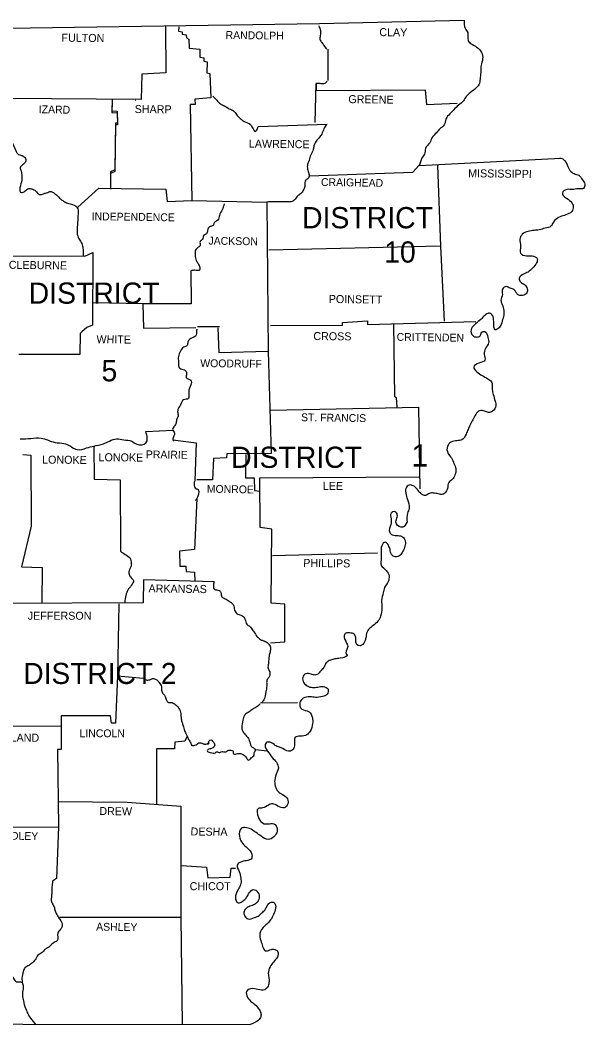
# Model space of a CAD drawing. Extents: x -33639 to 34530, y -17264 to 5867.
# Drawn here: x -15961 to -14292, y 2895 to 5867 of the extents above; entities that cross this region are included whole.
import ezdxf

# ---------------------------------------------------------------- set-up
doc = ezdxf.new("R2010")
doc.units = 0
for name, color, linetype in [('1', 7, 'Continuous'), ('2', 7, 'Continuous'), ('3', 7, 'Continuous')]:
    doc.layers.add(name, color=color, linetype=linetype)

msp = doc.modelspace()

# ---------------------------------------------------------------- linework, layer by layer
at = {"layer": '1'}
for p, q in [((-14780.6, 5436.9), (-14774, 5457.3)), ((-14779, 5443.5), (-14772.4, 5459.5)), ((-15436.7, 4960.3), (-15371.2, 4960.3)), ((-15250.6, 3847.5), (-15140.6, 3849.1))]:
    msp.add_line(p, q, dxfattribs=at)
for points in [[(-17667.8, 5841.4), (-16777.9, 5840.9), (-15996.9, 5842.5), (-15075.6, 5856.8), (-14648.6, 5866.7)], [(-15530.8, 5847.5), (-15529.7, 5711), (-15601.2, 5707.1), (-15603.4, 5632.3), (-16001.3, 5634.5)], [(-15491.2, 5846.9), (-15492.8, 5833.7), (-15481.8, 5832.1), (-15482.3, 5825.5), (-15469.7, 5822.7), (-15468.6, 5813.9), (-15462.5, 5810.1), (-15460.9, 5783.6), (-15429.5, 5780.3), (-15429.5, 5756.7), (-15418, 5755), (-15418, 5745.7), (-15408, 5742.9), (-15408.6, 5711), (-15399.8, 5709.3), (-15397.6, 5637.2), (-15444.4, 5632.8), (-15443.8, 5617.4), (-15458.1, 5616.9), (-15453.2, 5332.9), (-15231.4, 5327.9), (-15227.5, 4886.6), (-15372.3, 4882.7), (-15375, 4957)], [(-15051.4, 5780.9), (-15051.4, 5687.9)], [(-15088.8, 5564.1), (-15086.1, 5679.1), (-15086.1, 5658.7), (-14764.1, 5660.4), (-14759.7, 5617.4), (-14668.9, 5620.7)], [(-15688.2, 5630.6), (-15689.3, 5598.7), (-15673.9, 5597.6), (-15673.3, 5562.4), (-15678.8, 5562.4), (-15681, 5423.7), (-15693.7, 5418.2), (-15693.7, 5372)], [(-15688.2, 5625.7), (-15689.3, 5593.8), (-15673.9, 5592.7), (-15673.3, 5557.4), (-15678.8, 5557.4), (-15681, 5418.8), (-15693.7, 5413.3), (-15693.7, 5367)], [(-15619.4, 5629.5), (-15618.8, 5630.1)], [(-15257.3, 5551.9), (-15053.1, 5559.1)], [(-14780.6, 5436.9), (-14362.9, 5458.4)], [(-15105.4, 5406.7), (-14799.9, 5416.6), (-14781.7, 5437.5)], [(-14727.8, 5436.4), (-14718.5, 5198.1), (-14707.4, 4976.3)], [(-15790.5, 5313.1), (-15727.8, 5369.8), (-15529.7, 5367), (-15525.8, 5330.2), (-15453.7, 5332.9)], [(-15159.3, 5329.1), (-15226.4, 5329.1), (-15231.4, 5327.9)], [(-16052.5, 5170), (-15769.6, 5168.3), (-15745.4, 5179.9), (-15747.1, 4964.7), (-15763.6, 4957.6), (-15778.4, 4944.9), (-15783.4, 4940), (-15783.9, 4878.3), (-15963.9, 4878.3)], [(-14718.5, 5198.1), (-15225.3, 5186.5)], [(-15455.9, 5124.9), (-15454.8, 5028), (-15597.9, 5027.5), (-15744.9, 5030.2)], [(-15597.9, 5027.5), (-15595.7, 4955.4), (-15441.1, 4958.1)], [(-15220.9, 4963.6), (-15008.5, 4964.7), (-15007.9, 4972.4), (-14934.2, 4977.9), (-14934.2, 4966.4), (-14613.9, 4975.2)], [(-14857.1, 4966.4), (-14854.4, 4754.5), (-14849.4, 4751.2), (-14847.8, 4722.6)], [(-15436.7, 4951), (-15439.4, 4950.4)], [(-15227.5, 4886.6), (-15219.3, 4585), (-15350.3, 4584.4), (-15350.8, 4572.3), (-15388.8, 4570.1), (-15392.1, 4507.4), (-15438.3, 4507.4)], [(-15220.9, 4713.2), (-14783.9, 4722)], [(-14783.9, 4722), (-14779.5, 4481)], [(-15589.1, 4650.5), (-15508.8, 4654.3)], [(-15509.3, 4625.7), (-15440.5, 4616.9), (-15444.4, 4504.6)], [(-15952.9, 4581.7), (-15928.7, 4580), (-15928.1, 4369.8), (-15956.8, 4250.4), (-15895.7, 4247.6), (-15896.2, 4142.4)], [(-15743.2, 4605.5), (-15742.1, 4509), (-15664.5, 4507.4), (-15664, 4296)], [(-15294.1, 4581.7), (-15294.7, 4513.4), (-15269.4, 4513.4), (-15268.3, 4475.5), (-15252.3, 4473.8)], [(-15220.9, 4025.3), (-15178, 4028), (-15178.6, 4139.7), (-15218.7, 4142.5), (-15216.5, 4361), (-15251.2, 4365.9), (-15252.3, 4512.9), (-14782.8, 4516.2)], [(-15438.3, 4451.8), (-15444.9, 4301), (-15490.1, 4296), (-15489, 4251.5), (-15470.8, 4252), (-15470.2, 4236.6), (-15445.5, 4233.8), (-15444.7, 4207.3)], [(-15215.4, 4283.4), (-14905, 4291.1)], [(-15387.7, 4205.8), (-15595.7, 4211.3), (-15596.8, 4143.6), (-16017.8, 4141.9)], [(-15668.9, 4140.3), (-15673.3, 3927.3), (-15596.8, 3921.2)], [(-15673.3, 3927.3), (-15678.3, 3787.5), (-15690.9, 3787.5), (-15693.1, 3809), (-15839.5, 3809), (-15839.5, 3778.2)], [(-16035.5, 3779.8), (-15840.6, 3778.7)], [(-15839.5, 3778.7), (-15839, 3709.9), (-15850.5, 3709.4), (-15847.2, 3481)], [(-15467.5, 3749.5), (-15474.1, 3734.7), (-15503.3, 3731.9), (-15504.9, 3712.1), (-15557.2, 3712.1), (-15557.7, 3547.6)], [(-15405.8, 3725.3), (-15404.2, 3727), (-15402.5, 3728.6), (-15402.5, 3728.6)], [(-15848.9, 3555.8), (-15644.7, 3554.2), (-15486.2, 3542.1)], [(-15486.2, 3542.1), (-15486.2, 3212.9), (-15481.8, 2896.5)], [(-16096, 3480.4), (-15847.2, 3481)], [(-15847.2, 3481), (-15852.7, 3328), (-15864.8, 3320.3)], [(-15483.4, 3366.5), (-15409.7, 3362.1), (-15406.4, 3330.2), (-15339.8, 3332.4), (-15337.1, 3359.3), (-15324.4, 3359.3)], [(-17299.1, 3345), (-17298, 2899.8), (-15280.9, 2896.5)], [(-15843.9, 3213.5), (-15486.2, 3213.5)]]:
    msp.add_lwpolyline(points, dxfattribs=at)
for points in [[(-14648.6, 5866.7), (-14645.8, 5842.5), (-14638.1, 5829.9), (-14637, 5806.8), (-14627.6, 5796.9), (-14611.7, 5786.9), (-14597.4, 5771), (-14594.1, 5752.3), (-14598.5, 5733), (-14599.6, 5711.5), (-14601.8, 5692.8), (-14605.1, 5675.8), (-14618.3, 5662), (-14630.9, 5652.1), (-14642.5, 5640.6), (-14650.8, 5628.4), (-14665.1, 5615.2), (-14679.4, 5601.5), (-14690.9, 5589.4), (-14702.5, 5574), (-14708, 5556.9), (-14720.7, 5544.8), (-14730.6, 5533.8), (-14743.8, 5518.9), (-14750.4, 5504.1), (-14763, 5487), (-14765.8, 5470.5), (-14774, 5457.3), (-14774.6, 5455.1)], [(-15078.4, 5849.7), (-15073.4, 5835.9), (-15074, 5821.1), (-15074, 5807.3), (-15066.8, 5798), (-15059.7, 5786.4), (-15054.2, 5781.4)], [(-15053.6, 5686.2), (-15060.8, 5679.1), (-15074.5, 5679.1), (-15086.1, 5679.1)], [(-15391.5, 5642.2), (-15379.4, 5629.5), (-15369, 5619.1), (-15356.9, 5613), (-15342.6, 5604.8), (-15329.9, 5598.2), (-15321.6, 5587.7), (-15310.1, 5576.2), (-15298.5, 5566.8), (-15280.4, 5558), (-15274.3, 5548.6), (-15266.1, 5537.1), (-15257.3, 5551.9)], [(-15054.7, 5558.5), (-15063, 5545.3), (-15069.6, 5529.9), (-15082.8, 5512.3), (-15092.7, 5495.3), (-15094.3, 5483.7), (-15102.1, 5468.3), (-15106.5, 5452.9), (-15111.4, 5439.7), (-15111.4, 5425.9), (-15107.6, 5412.2), (-15108.7, 5399.5), (-15116.9, 5393.4), (-15119.1, 5377.5), (-15122.4, 5366.5), (-15129.6, 5355.5), (-15140, 5347.2), (-15151, 5334.6), (-15159.3, 5329.1)], [(-16025.5, 5511.2), (-16003.5, 5507.4), (-15990.3, 5512.3), (-15981, 5498), (-15976, 5487), (-15967.8, 5471), (-15954.6, 5466.1), (-15944.6, 5457.3), (-15944.6, 5447.9), (-15953.4, 5439.1), (-15960.1, 5430.3), (-15957.9, 5419.9), (-15955.7, 5405.5), (-15955.7, 5391.8), (-15959, 5379.1), (-15961.7, 5367.6), (-15959, 5357.7), (-15948.5, 5359.3), (-15937.5, 5367.6), (-15925.9, 5367.6), (-15914.9, 5361.5), (-15903.4, 5351.1), (-15891.8, 5353.3), (-15882.5, 5356), (-15869.2, 5359.9), (-15859.9, 5354.9), (-15851.6, 5348.3), (-15841.7, 5337.9), (-15832.4, 5331.3), (-15820.3, 5325.2), (-15805.4, 5321.3), (-15791.6, 5312), (-15789.4, 5296), (-15790, 5282.3), (-15791.1, 5265.2), (-15792.2, 5246.5), (-15790.5, 5228.3), (-15784.5, 5216.2), (-15776.8, 5201.9), (-15774.6, 5188.7), (-15775.1, 5167.8)], [(-14369, 5457.8), (-14362.9, 5458.4), (-14344.2, 5438.6), (-14336, 5422.1), (-14323.9, 5412.7), (-14310.1, 5407.8), (-14299.6, 5395.1), (-14292.5, 5381.3), (-14296.3, 5369.2), (-14311.7, 5368.1), (-14328.8, 5365.4), (-14345.3, 5365.9), (-14358.5, 5354.9), (-14346.4, 5340.1), (-14330.5, 5326.3), (-14326.1, 5311.4), (-14334.9, 5297.1), (-14352.5, 5289.4), (-14369.5, 5282.8), (-14384.9, 5269.6), (-14392.1, 5257), (-14409.2, 5251.5), (-14426.8, 5246.5), (-14442.2, 5244.8), (-14459.8, 5241.5), (-14476.9, 5233.3), (-14484, 5219), (-14481.8, 5198.6), (-14482.4, 5177.2), (-14464.2, 5170), (-14448.2, 5169.4), (-14432.8, 5161.2), (-14434.5, 5149.1), (-14446, 5133.7), (-14459.8, 5121.6), (-14473.5, 5115.5), (-14486.2, 5104), (-14481.8, 5092.4), (-14470.2, 5084.7), (-14462, 5072), (-14463.1, 5060.5), (-14476.3, 5052.2), (-14490.6, 5055.5), (-14501.1, 5069.3), (-14513.2, 5073.7), (-14523.6, 5078.6), (-14535.7, 5071.5), (-14535.7, 5055.5), (-14540.1, 5038.5), (-14536.3, 5025.8), (-14531.3, 5008.2), (-14531.9, 4995), (-14536.3, 4976.3), (-14545.6, 4957), (-14556.7, 4951), (-14561.1, 4971.9), (-14563.3, 4988.9), (-14569.9, 4998.8), (-14578.7, 4999.4), (-14590.2, 4991.1), (-14602.9, 4978.5), (-14618.8, 4964.7), (-14628.2, 4951), (-14623.2, 4933.9), (-14611.1, 4929.5), (-14601.8, 4932.8), (-14596.8, 4943.8), (-14587.5, 4945.5), (-14578.7, 4928.4)], [(-15357.4, 5323), (-15364, 5305.9), (-15371.7, 5289.4), (-15376.7, 5275.1), (-15387.1, 5266.9), (-15390.4, 5259.2), (-15399.8, 5255.9), (-15406.9, 5244.8), (-15410.3, 5234.9), (-15418, 5230.5), (-15421.8, 5218.4), (-15429, 5211.8), (-15428.4, 5200.8), (-15436.7, 5193.1), (-15443.3, 5184.3), (-15443.3, 5172.2), (-15440.5, 5156.2), (-15435, 5146.9), (-15430.1, 5134.8), (-15430.6, 5127.1), (-15444.4, 5127.1), (-15455.9, 5124.9)], [(-15439.4, 4950.4), (-15442.2, 4932.2), (-15452.6, 4927.3), (-15464.7, 4915.2), (-15467.5, 4904.2), (-15477.4, 4899.8), (-15486.7, 4888.2), (-15492.8, 4872.3), (-15492.8, 4855.7), (-15489, 4837), (-15475.2, 4832.1), (-15468.6, 4821.1), (-15469.7, 4809.5), (-15456.5, 4801.8), (-15454.3, 4795.2), (-15456.5, 4788.1), (-15462.5, 4767.7), (-15462, 4753.9), (-15463.1, 4747.9), (-15477.9, 4744), (-15486.7, 4729.2), (-15492.8, 4718.7), (-15495, 4704.9), (-15493.4, 4695), (-15497.8, 4687.3), (-15499.4, 4675.8), (-15504.9, 4665.9), (-15509.9, 4656.5), (-15504.4, 4645.5), (-15506, 4637.8), (-15509.3, 4625.7), (-15506.6, 4621.8)], [(-14578.7, 4928.4), (-14576.5, 4912.4), (-14585.8, 4895.4), (-14589.1, 4878.3), (-14587.5, 4861.2), (-14605.1, 4851.9), (-14620.5, 4840.9), (-14611.7, 4827.7), (-14595.2, 4815.6), (-14578.7, 4806.2), (-14568.2, 4796.9), (-14565.5, 4774.3), (-14562.7, 4760), (-14557.2, 4740.2), (-14555, 4726.4), (-14564.9, 4709.9), (-14576.5, 4706.6), (-14588.6, 4710.5), (-14602.9, 4711.6), (-14614.4, 4700.5), (-14622.7, 4685.1), (-14630.9, 4669.7), (-14637, 4656.5), (-14643.1, 4642.2), (-14655.2, 4625.7), (-14670, 4622.9), (-14687.6, 4618.5), (-14698.1, 4606.4), (-14696.4, 4586.1), (-14686.5, 4572.3), (-14678.8, 4555.3), (-14673.3, 4540.4), (-14676.1, 4521.7), (-14683.8, 4507.9), (-14693.7, 4499.7), (-14698.1, 4482.1), (-14705.2, 4468.8), (-14711.9, 4464.4), (-14725.1, 4465.5), (-14739.4, 4468.3), (-14751.5, 4467.2), (-14763, 4461.1), (-14774.6, 4465), (-14786.7, 4478.2), (-14796.6, 4488.1), (-14807.6, 4492), (-14819.2, 4485.9), (-14821.4, 4467.7), (-14815.9, 4449), (-14810.9, 4423.7), (-14815.9, 4408.3), (-14817.5, 4383)], [(-15960.6, 4628.4), (-15928.7, 4629.6), (-15898.4, 4630.7), (-15879.2, 4625.1), (-15857.1, 4618), (-15831.3, 4614.7), (-15813.1, 4607.5), (-15791.6, 4596.5), (-15764.1, 4601.5), (-15742.7, 4607), (-15714.6, 4614.1), (-15696.4, 4621.8), (-15675.5, 4628.5), (-15654.6, 4625.7), (-15630.9, 4621.3), (-15616.1, 4612.5), (-15589.1, 4616.3), (-15589.1, 4650.5)], [(-15444.4, 4504.6), (-15446.6, 4493.6), (-15442.2, 4482.1), (-15434.5, 4478.2), (-15433.4, 4467.2), (-15436.1, 4456.2), (-15438.3, 4451.8), (-15443.3, 4445.2)], [(-14817.5, 4383), (-14830.2, 4367), (-14848.9, 4376.9), (-14848.9, 4390.1), (-14846.1, 4403.9), (-14852.7, 4412.7), (-14864.3, 4408.9), (-14864.3, 4391.8), (-14865.4, 4375.3), (-14868.7, 4351.6), (-14861, 4344.5), (-14843.4, 4342.3), (-14830.7, 4339), (-14823, 4326.3), (-14823.6, 4310.9), (-14829.6, 4296), (-14838.4, 4283.9), (-14852.2, 4279.5), (-14863.2, 4286.7), (-14867.6, 4301), (-14872.6, 4313.6), (-14881.9, 4323), (-14891.8, 4312.5), (-14894, 4293.3), (-14893.5, 4276.8), (-14893.5, 4254.2), (-14879.2, 4239.3), (-14870.4, 4222.3), (-14873.1, 4206.9), (-14883.6, 4188.7), (-14888, 4172.8), (-14892.4, 4151.3), (-14891.8, 4127.6), (-14895.7, 4104.5), (-14903.4, 4089.1), (-14917.7, 4076.4), (-14927, 4068.2), (-14934.7, 4059.9), (-14938.6, 4043.4), (-14941.3, 4031.9), (-14951.8, 4018.1), (-14960.1, 4017), (-14966.7, 4022.5), (-14968.9, 4031.9), (-14968.9, 4041.2), (-14973.3, 4050.6), (-14987, 4054.4), (-14998, 4053.9), (-15003, 4046.2), (-14995.8, 4024.7), (-14993.1, 4011), (-14996.9, 3992.2), (-14994.7, 3990), (-15014.5, 3979.6), (-15030.5, 3977.9), (-15043.7, 3974.1), (-15056.4, 3965.8), (-15062.4, 3953.7), (-15071.2, 3943.8), (-15078.9, 3934.5), (-15089.4, 3930.1), (-15101, 3932.3), (-15116.4, 3933.9), (-15125.2, 3922.9), (-15122.4, 3906.9), (-15112, 3897.6), (-15096.5, 3893.2), (-15080.6, 3894.3), (-15065.2, 3895.9), (-15050.9, 3888.2), (-15053.6, 3873.4), (-15067.4, 3866.2), (-15087.7, 3864), (-15104.3, 3865.7), (-15124.1, 3861.3), (-15134, 3848.6), (-15128.5, 3829.3), (-15107, 3821.6), (-15097.1, 3803.5), (-15096.5, 3786.4), (-15103.7, 3763.8), (-15113.6, 3753.4), (-15132.9, 3749), (-15147.7, 3746.2), (-15149.9, 3720.9), (-15156.5, 3708.3), (-15168.1, 3704.4), (-15184.6, 3712.7), (-15194.5, 3716.5), (-15206.6, 3722), (-15222, 3731.4), (-15233.6, 3729.7), (-15230.3, 3705.5), (-15229.2, 3704.4), (-15216, 3686.2), (-15202.8, 3671.9), (-15196.7, 3654.9)], [(-15664, 4296), (-15650.2, 4286.7), (-15635.9, 4275.7), (-15632, 4260.8), (-15633.1, 4250.4), (-15637.5, 4241.6), (-15638.6, 4227.8), (-15632, 4217.9), (-15626, 4209.6), (-15632, 4194.8), (-15642.5, 4181), (-15648, 4165.6), (-15651.6, 4144.3)], [(-15387.7, 4205.8), (-15386, 4183.2), (-15372.8, 4179.9), (-15367.3, 4173.9), (-15364.6, 4161.2), (-15355.2, 4155.7), (-15342.6, 4148), (-15334.9, 4142.5), (-15329.3, 4133.7), (-15326, 4119.4), (-15317.2, 4110), (-15305.1, 4105.6), (-15296.3, 4095.2), (-15290.8, 4080.3), (-15282, 4073.7), (-15273.2, 4062.1), (-15268.8, 4057.2), (-15261.1, 4044), (-15253.4, 4037.4), (-15247.9, 4033.5), (-15239.1, 4030.8), (-15228.1, 4023.6), (-15220.9, 4012.6), (-15220.9, 4004.3), (-15223.7, 3991.7), (-15225.9, 3978.5), (-15227, 3963.6), (-15228.1, 3950.4), (-15223.1, 3939.4), (-15225.9, 3922.9), (-15231.4, 3914.1), (-15231.9, 3902), (-15233.6, 3883.8), (-15235.8, 3873.4), (-15240.7, 3856.3), (-15247.9, 3847.5)], [(-15596.8, 3921.2), (-15588.6, 3915.7), (-15577, 3916.3), (-15569.3, 3919.6), (-15563.2, 3919), (-15555, 3914.1), (-15549.5, 3907.5), (-15545.6, 3902.5), (-15542.9, 3894.8), (-15542.9, 3887.7), (-15540.1, 3877.8), (-15536.8, 3873.9), (-15532.4, 3866.8), (-15529.7, 3860.2), (-15528, 3855.8), (-15522, 3848.6), (-15516.5, 3849.1), (-15511.5, 3848.6), (-15504.9, 3844.7), (-15495, 3837), (-15493.4, 3834.8), (-15486.7, 3820.5), (-15485.6, 3811.7), (-15484.5, 3800.2), (-15482.3, 3789.2), (-15477.9, 3777.1), (-15475.7, 3768.8), (-15470.8, 3757.2), (-15467.5, 3749.5), (-15463.1, 3739.6), (-15456.5, 3728.6), (-15453.7, 3722), (-15444.4, 3722.6), (-15437.8, 3725.3), (-15432.8, 3729.7), (-15426.8, 3729.2), (-15420.2, 3727), (-15411.4, 3725.3), (-15405.8, 3728.6), (-15403.1, 3730.8), (-15402.5, 3735.8), (-15397.6, 3738.5), (-15392.1, 3734.7), (-15386, 3725.9), (-15386, 3720.4), (-15388.2, 3717.1), (-15395.4, 3712.7), (-15405.3, 3709.4), (-15408, 3705.5), (-15398.7, 3701.1), (-15383.8, 3700), (-15380, 3703.3), (-15370.1, 3700.6), (-15366.2, 3703.3), (-15353, 3702.8), (-15347, 3707.2), (-15334.9, 3706.6), (-15331, 3703.9), (-15331, 3698.9), (-15321.1, 3696.7), (-15313.9, 3698.4), (-15304.6, 3695.6), (-15296.3, 3691.2), (-15291.9, 3685.1), (-15286.4, 3678.5), (-15281.5, 3680.2), (-15277.6, 3685.1), (-15269.4, 3693.9), (-15269.4, 3699.5), (-15267.2, 3703.3), (-15264.4, 3708.8)], [(-15251.7, 3844.2), (-15263.3, 3834.8), (-15273.2, 3829.3), (-15283.7, 3821.6), (-15296.3, 3812.3), (-15302.4, 3796.3), (-15305.7, 3774.3), (-15301.3, 3761.1), (-15291.4, 3749.5), (-15284.8, 3740.2), (-15279.8, 3723.7), (-15267.7, 3712.1), (-15263.9, 3710.5)], [(-15196.7, 3654.9), (-15202.2, 3642.2), (-15208.3, 3620.2), (-15206.6, 3601.5), (-15198.4, 3585.5), (-15185.2, 3576.7), (-15170.8, 3564.1), (-15171.9, 3544.8), (-15180.2, 3537.6), (-15199.5, 3542.6), (-15214.3, 3549.2), (-15227, 3545.4), (-15244, 3537.1), (-15256.7, 3535.4), (-15256.2, 3509), (-15239.1, 3490.3), (-15224.2, 3490.3), (-15207.2, 3488.1), (-15201.1, 3468.3), (-15211, 3451.8), (-15227.5, 3443.5), (-15248.4, 3453.4), (-15263.3, 3463.9), (-15278.2, 3473.8), (-15296.9, 3478.8), (-15307.3, 3476.6), (-15312.3, 3453.4), (-15303.5, 3432.5), (-15289.2, 3418.2), (-15276, 3399.5), (-15278.2, 3385.8), (-15288.1, 3381.9), (-15305.7, 3378), (-15316.1, 3372.5), (-15318.9, 3368.1), (-15313.4, 3349.4), (-15308.4, 3329.1), (-15308.4, 3313.7), (-15314.5, 3299.3), (-15323.8, 3277.3), (-15322.7, 3263), (-15316.1, 3256.4), (-15307.9, 3258.6), (-15296.9, 3266.3), (-15289.7, 3275.1), (-15283.7, 3286.1), (-15272.1, 3295.5), (-15257.8, 3287.2), (-15254.5, 3270.2), (-15262.8, 3255.3), (-15274.3, 3248.7), (-15288.6, 3243.2), (-15299.1, 3231.1), (-15296.3, 3216.8), (-15288.1, 3209.1), (-15267.7, 3212.9), (-15253.9, 3219), (-15246.2, 3226.7), (-15236.9, 3236.1), (-15231.9, 3245.4), (-15224.8, 3255.3), (-15212.1, 3258.1), (-15206.1, 3249.8), (-15208.3, 3231.1), (-15216, 3213.5), (-15226.4, 3198.6), (-15238, 3188.2), (-15252.3, 3165.6), (-15249.5, 3144.7), (-15244, 3127.6), (-15236.3, 3114.4), (-15223.1, 3117.2), (-15208.3, 3118.8), (-15199.5, 3111.7), (-15200.6, 3096.3), (-15211.6, 3081.4), (-15222, 3067.1), (-15227.5, 3047.3), (-15225.3, 3033.5), (-15225.3, 3020.9), (-15229.7, 3007.1), (-15237.4, 2999.4), (-15257.8, 3000), (-15279.3, 3002.2), (-15290.8, 2995.6), (-15288.6, 2976.8), (-15276, 2963.1), (-15267.2, 2955.9), (-15254.5, 2940.5), (-15249, 2927.9), (-15250.6, 2916.8), (-15258.4, 2907.5), (-15280.9, 2896.5)], [(-15864.8, 3320.3), (-15866.5, 3303.2), (-15867, 3287.2), (-15868.1, 3271.8), (-15868.1, 3260.3), (-15861.5, 3247.6), (-15857.7, 3235.5), (-15853.8, 3225), (-15846.1, 3211.3), (-15839, 3200.8), (-15836.8, 3186), (-15841.2, 3178.3), (-15849.4, 3166.7), (-15850, 3145.8), (-15859.9, 3139.2), (-15872.5, 3128.2), (-15879.7, 3123.2), (-15887.4, 3118.3), (-15895.7, 3109.5), (-15907.8, 3101.2), (-15916.6, 3087.5), (-15926.5, 3077), (-15934.7, 3071.5), (-15946.3, 3064.3), (-15951.2, 3053.3), (-15955.1, 3033), (-15953.4, 3018.1), (-15951.2, 3004.9), (-15954, 2988.4), (-15951.2, 2970.2), (-15948.5, 2955.9), (-15944.1, 2943.3), (-15938, 2929), (-15930.3, 2915.7), (-15913.8, 2895.4)], [(-16413.5, 3193.1), (-16404.7, 3199.2), (-16396.5, 3202.5), (-16388.2, 3200.8), (-16379.4, 3199.7), (-16371.7, 3200.8), (-16361.8, 3199.2), (-16353.6, 3194.2), (-16344.2, 3190.4), (-16334.8, 3190.4), (-16326.6, 3190.4), (-16319.4, 3185.4), (-16306.2, 3186), (-16295.2, 3190.4), (-16284.2, 3193.7), (-16269.4, 3195.3), (-16256.1, 3186), (-16246.8, 3178.3), (-16239.1, 3169.5), (-16233.6, 3159.6), (-16227.5, 3154.1), (-16217.6, 3150.2), (-16209.9, 3148.5), (-16200.6, 3145.8), (-16195.6, 3143.6), (-16191.2, 3133.1), (-16184, 3118.8), (-16170.3, 3113.9), (-16153.2, 3120.5), (-16139.5, 3124.3), (-16129.6, 3127.6), (-16123.5, 3129.8), (-16118, 3130.4), (-16119.7, 3131.5), (-16113.1, 3133.1), (-16107, 3128.7), (-16103.1, 3122.7), (-16096.5, 3113.9), (-16090.5, 3106.2), (-16084.4, 3103.4), (-16078.4, 3106.7), (-16070.1, 3104), (-16063, 3101.2), (-16054.7, 3099), (-16047.6, 3098.5), (-16038.2, 3096.3), (-16031, 3092.4), (-16024.4, 3088.6), (-16017.8, 3081.4), (-16011.2, 3070.4), (-16009, 3061.6), (-16001.3, 3052.8), (-15994.2, 3052.8), (-15983.7, 3038.5), (-15979.9, 3033), (-15971.6, 3023.1), (-15965.6, 3023.1), (-15954, 3020.9)]]:
    msp.add_spline(points, degree=3, dxfattribs=at)
at = {"layer": '3'}
msp.add_line((-15265.5, 3709.9), (-15230.8, 3705.5), dxfattribs=at)

# ---------------------------------------------------------------- texts
at = {"layer": '1'}
msp.add_text('1', height=66, dxfattribs=at).set_placement((-14804.3, 4546.4))
at = {"layer": '2'}
for s, height, rotation, p in [('FULTON', 23.66, 359.4996, (-15838.4, 5802.9)), ('RANDOLPH', 23.11, 359.2583, (-15353.6, 5811.2)), ('CLAY', 23.66, 359.2258, (-14899.5, 5819.4)), ('SHARP', 23.66, 359.3905, (-15622.1, 5592.1)), ('GREENE', 23.67, 359.2361, (-14990.9, 5621.3)), ('IZARD', 23.11, 358.9258, (-15905.6, 5591.6)), ('LAWRENCE', 23.67, 359.2678, (-15284.8, 5489.8)), ('MISSISSIPPI', 23.66, 359.3097, (-14637, 5402.2)), ('CRAIGHEAD', 23.11, 359.1159, (-15071.8, 5376.4)), ('INDEPENDENCE', 23.108, 359.2187, (-15749.3, 5275.1)), ('JACKSON', 23.11, 359.1352, (-15404.2, 5203)), ('CLEBURNE', 23.66, 359.2535, (-15994.2, 5131.5)), ('POINSETT', 23.66, 359.1987, (-15048.8, 5030.4)), ('WHITE', 23.67, 359.3139, (-15735, 4911.3)), ('CROSS', 23.66, 359.3839, (-15094.3, 4920.7)), ('CRITTENDEN', 23.11, 359.213, (-14848.3, 4918.5)), ('WOODRUFF', 23.11, 359.2748, (-15428.4, 4840.9)), ('ST. FRANCIS', 23.108, 359.2216, (-15130.7, 4680.7)), ('LONOKE', 23.67, 359.4974, (-15895.7, 4555.3)), ('LONOKE', 23.67, 359.4974, (-15728.9, 4562.4)), ('PRAIRIE', 23.11, 359.2116, (-15589.1, 4571.2)), ('MONROE', 23.11, 359.0331, (-15409.1, 4469.4)), ('LEE', 23.67, 359.4327, (-15066.3, 4477.7)), ('PHILLIPS', 23.66, 359.3179, (-15124.1, 4249.8)), ('ARKANSAS', 23.66, 359.2678, (-15581.4, 4174.4)), ('CLEVELAND', 23.67, 359.3377, (-16092.7, 3734.7)), ('DREW', 23.66, 359.2258, (-15726.7, 3516.2)), ('DESHA', 23.66, 359.3704, (-15457, 3455.6)), ('BRADLEY', 23.11, 359.1449, (-16051.4, 3444.1)), ('ASHLEY', 23.11, 359.2361, (-15736.1, 3174.4))]:
    msp.add_text(s, height=height, rotation=rotation, dxfattribs=at).set_placement(p)
for s, height, p in [('JEFFERSON', 23.67, (-15938, 4093.5)), ('LINCOLN', 23.11, (-15785, 3746.2)), ('CHICOT', 23.67, (-15459.8, 3293.8))]:
    msp.add_text(s, height=height, dxfattribs=at).set_placement(p)
at = {"layer": '3'}
for s, height, p in [('DISTRICT', 62.74, (-15127.6, 5251.1)), ('10', 62.74, (-14885.1, 5149.6)), ('DISTRICT', 62.74, (-15935.3, 5028)), ('5', 62.7, (-15720.1, 4798.5)), ('DISTRICT', 62.74, (-15337.1, 4542.6)), ('DISTRICT 2', 62.19, (-15951.2, 3903.6))]:
    msp.add_text(s, height=height, dxfattribs=at).set_placement(p)

doc.saveas('drawing.dxf')
